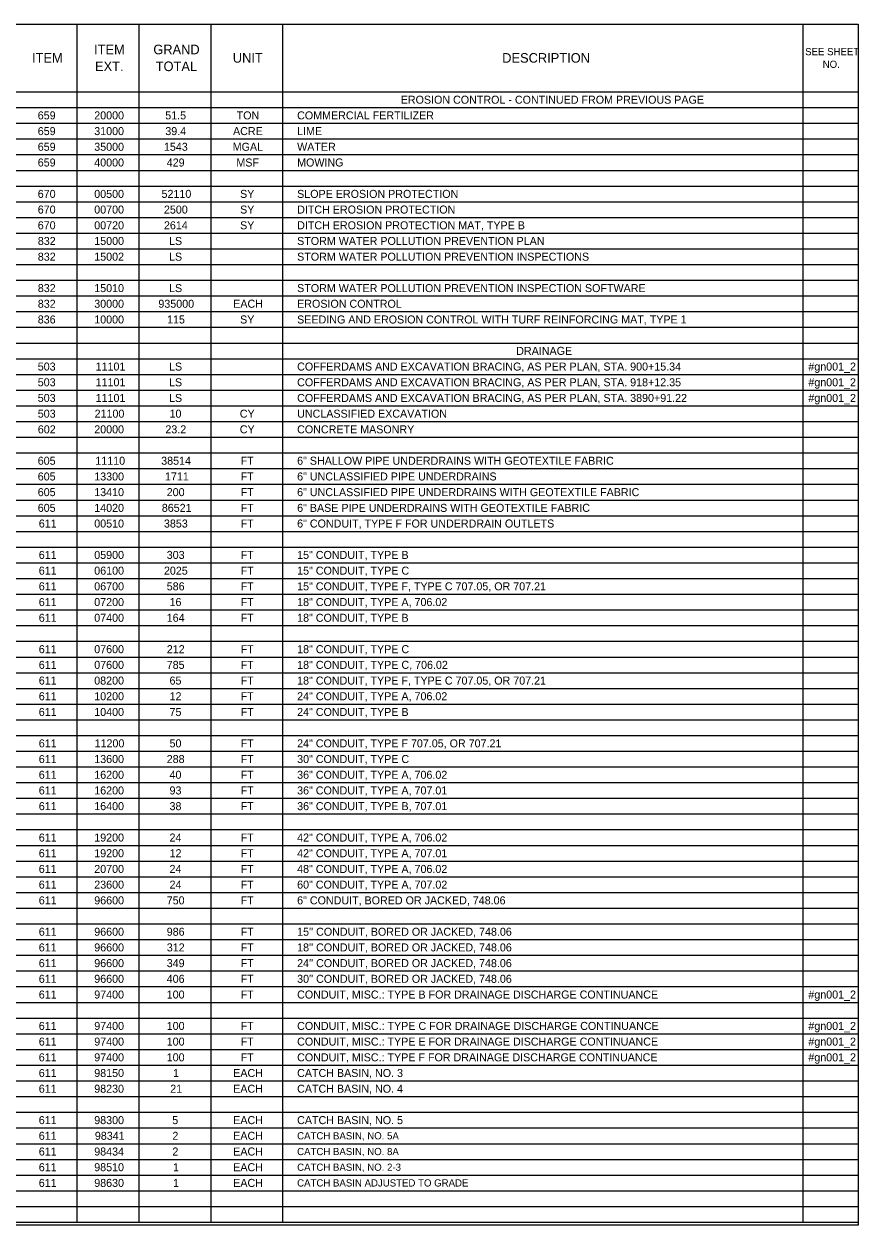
# Model space of a CAD drawing. Extents: x -542 to 295, y -281 to 32.
# Drawn here: x -400.45 to -385.84, y -40.59 to -19.59 of the extents above; entities that cross this region are included whole.
import ezdxf

# ---------------------------------------------------------------- set-up
doc = ezdxf.new("R2010")
doc.units = 0
for name, color, linetype in [('SC_Scratch1', 7, 'Continuous'), ('SH_Data', 7, 'Continuous'), ('SH_Text', 7, 'Continuous')]:
    doc.layers.add(name, color=color, linetype=linetype)

msp = doc.modelspace()

# ---------------------------------------------------------------- linework, layer by layer
at = {"layer": 'SC_Scratch1'}
msp.add_lwpolyline([(-416.359, -19.593), (-385.859, -19.593), (-385.859, -40.593), (-416.359, -40.593)], close=True, dxfattribs=at)
at = {"layer": 'SH_Data'}
for p, q in [((-416.359, -19.593), (-385.859, -19.593)), ((-399.523, -19.593), (-399.523, -40.543)), ((-398.437, -19.593), (-398.437, -40.543)), ((-397.182, -19.593), (-397.182, -40.543)), ((-395.926, -19.593), (-395.926, -40.543)), ((-386.827, -19.593), (-386.827, -40.543)), ((-385.859, -19.593), (-385.859, -40.543)), ((-416.359, -20.778), (-385.859, -20.778)), ((-416.359, -21.053), (-385.859, -21.053)), ((-416.359, -21.327), (-385.859, -21.327)), ((-416.359, -21.602), (-385.859, -21.602)), ((-416.359, -21.876), (-385.859, -21.876)), ((-416.359, -22.151), (-385.859, -22.151)), ((-416.359, -22.425), (-385.859, -22.425)), ((-416.359, -22.7), (-385.859, -22.7)), ((-416.359, -22.975), (-385.859, -22.975)), ((-416.359, -23.249), (-385.859, -23.249)), ((-416.359, -23.524), (-385.859, -23.524)), ((-416.359, -23.798), (-385.859, -23.798)), ((-416.359, -24.073), (-385.859, -24.073)), ((-416.359, -24.347), (-385.859, -24.347)), ((-416.359, -24.622), (-385.859, -24.622)), ((-416.359, -24.896), (-385.859, -24.896)), ((-416.359, -25.171), (-385.859, -25.171)), ((-416.359, -25.445), (-385.859, -25.445)), ((-416.359, -25.72), (-385.859, -25.72)), ((-416.359, -25.994), (-385.859, -25.994)), ((-416.359, -26.269), (-385.859, -26.269)), ((-416.359, -26.543), (-385.859, -26.543)), ((-416.359, -26.818), (-385.859, -26.818)), ((-416.359, -27.092), (-385.859, -27.092)), ((-416.359, -27.367), (-385.859, -27.367)), ((-416.359, -27.641), (-385.859, -27.641)), ((-416.359, -27.916), (-385.859, -27.916)), ((-416.359, -28.19), (-385.859, -28.19)), ((-416.359, -28.465), (-385.859, -28.465)), ((-416.359, -28.739), (-385.859, -28.739)), ((-416.359, -29.014), (-385.859, -29.014)), ((-416.359, -29.288), (-385.859, -29.288)), ((-416.359, -29.563), (-385.859, -29.563)), ((-416.359, -29.837), (-385.859, -29.837)), ((-416.359, -30.112), (-385.859, -30.112)), ((-416.359, -30.386), (-385.859, -30.386)), ((-416.359, -30.661), (-385.859, -30.661)), ((-416.359, -30.935), (-385.859, -30.935)), ((-416.359, -31.21), (-385.859, -31.21)), ((-416.359, -31.484), (-385.859, -31.484)), ((-416.359, -31.759), (-385.859, -31.759)), ((-416.359, -32.033), (-385.859, -32.033)), ((-416.359, -32.308), (-385.859, -32.308)), ((-416.359, -32.582), (-385.859, -32.582)), ((-416.359, -32.857), (-385.859, -32.857)), ((-416.359, -33.131), (-385.859, -33.131)), ((-416.359, -33.406), (-385.859, -33.406)), ((-416.359, -33.68), (-385.859, -33.68)), ((-416.359, -33.955), (-385.859, -33.955)), ((-416.359, -34.229), (-385.859, -34.229)), ((-416.359, -34.504), (-385.859, -34.504)), ((-416.359, -34.778), (-385.859, -34.778)), ((-416.359, -35.053), (-385.859, -35.053)), ((-416.359, -35.327), (-385.859, -35.327)), ((-416.359, -35.602), (-385.859, -35.602)), ((-416.359, -35.876), (-385.859, -35.876)), ((-416.359, -36.151), (-385.859, -36.151)), ((-416.359, -36.425), (-385.859, -36.425)), ((-416.359, -36.7), (-385.859, -36.7)), ((-416.359, -36.975), (-385.859, -36.975)), ((-416.359, -37.249), (-385.859, -37.249)), ((-416.359, -37.524), (-385.859, -37.524)), ((-416.359, -37.798), (-385.859, -37.798)), ((-416.359, -38.073), (-385.859, -38.073)), ((-416.359, -38.347), (-385.859, -38.347)), ((-416.359, -38.622), (-385.859, -38.622)), ((-416.359, -38.896), (-385.859, -38.896)), ((-416.359, -39.171), (-385.859, -39.171)), ((-416.359, -39.445), (-385.859, -39.445)), ((-416.359, -39.72), (-385.859, -39.72)), ((-416.359, -39.994), (-385.859, -39.994)), ((-416.359, -40.269), (-385.859, -40.269)), ((-416.359, -40.543), (-385.859, -40.543))]:
    msp.add_line(p, q, dxfattribs=at)

# ---------------------------------------------------------------- texts
at = {"layer": 'SH_Text'}
for s, height, p in [('ITEM', 0.168, (-400.307, -20.269)), ('ITEM', 0.168, (-399.222, -20.122)), ('GRAND ', 0.168, (-398.186, -20.122)), ('UNIT', 0.168, (-396.795, -20.269)), ('DESCRIPTION', 0.168, (-392.083, -20.269)), ('SEE SHEET ', 0.126, (-386.784, -20.138)), ('EXT.', 0.168, (-399.205, -20.416)), ('TOTAL', 0.168, (-398.144, -20.416)), ('NO.', 0.126, (-386.477, -20.359)), ('EROSION CONTROL - CONTINUED FROM PREVIOUS PAGE', 0.14, (-393.858, -20.986)), ('659', 0.14, (-400.207, -21.26)), ('20000', 0.14, (-399.219, -21.26)), ('51.5', 0.14, (-397.977, -21.26)), ('TON', 0.14, (-396.728, -21.26)), ('COMMERCIAL FERTILIZER', 0.14, (-395.67, -21.26)), ('659', 0.14, (-400.207, -21.535)), ('31000', 0.14, (-399.219, -21.535)), ('39.4', 0.14, (-397.976, -21.535)), ('ACRE', 0.14, (-396.791, -21.535)), ('LIME', 0.14, (-395.67, -21.535)), ('659', 0.14, (-400.207, -21.809)), ('35000', 0.14, (-399.219, -21.809)), ('1543', 0.14, (-398, -21.809)), ('MGAL', 0.14, (-396.797, -21.809)), ('WATER', 0.14, (-395.67, -21.809)), ('659', 0.14, (-400.207, -22.084)), ('40000', 0.14, (-399.219, -22.084)), ('429', 0.14, (-397.951, -22.084)), ('MSF', 0.14, (-396.733, -22.084)), ('MOWING', 0.14, (-395.67, -22.084)), ('670', 0.14, (-400.207, -22.633)), ('00500', 0.14, (-399.219, -22.633)), ('52110', 0.14, (-398.042, -22.633)), ('SY', 0.14, (-396.668, -22.633)), ('SLOPE EROSION PROTECTION', 0.14, (-395.67, -22.633)), ('670', 0.14, (-400.207, -22.907)), ('00700', 0.14, (-399.219, -22.907)), ('2500', 0.14, (-398, -22.907)), ('SY', 0.14, (-396.668, -22.907)), ('DITCH EROSION PROTECTION', 0.14, (-395.67, -22.907)), ('670', 0.14, (-400.207, -23.182)), ('00720', 0.14, (-399.219, -23.182)), ('2614', 0.14, (-398, -23.182)), ('SY', 0.14, (-396.668, -23.182)), ('DITCH EROSION PROTECTION MAT, TYPE B', 0.14, (-395.67, -23.182)), ('832', 0.14, (-400.206, -23.456)), ('15000', 0.14, (-399.219, -23.456)), ('LS', 0.14, (-397.911, -23.456)), ('STORM WATER POLLUTION PREVENTION PLAN', 0.14, (-395.67, -23.456)), ('832', 0.14, (-400.206, -23.731)), ('15002', 0.14, (-399.219, -23.731)), ('LS', 0.14, (-397.911, -23.731)), ('STORM WATER POLLUTION PREVENTION INSPECTIONS', 0.14, (-395.67, -23.731)), ('832', 0.14, (-400.206, -24.28)), ('15010', 0.14, (-399.219, -24.28)), ('LS', 0.14, (-397.911, -24.28)), ('STORM WATER POLLUTION PREVENTION INSPECTION SOFTWARE', 0.14, (-395.67, -24.28)), ('832', 0.14, (-400.206, -24.554)), ('30000', 0.14, (-399.219, -24.554)), ('935000', 0.14, (-398.097, -24.554)), ('EACH', 0.14, (-396.788, -24.554)), ('EROSION CONTROL', 0.14, (-395.67, -24.554)), ('836', 0.14, (-400.207, -24.829)), ('10000', 0.14, (-399.219, -24.829)), ('115', 0.14, (-397.945, -24.829)), ('SY', 0.14, (-396.668, -24.829)), ('SEEDING AND EROSION CONTROL WITH TURF REINFORCING MAT, TYPE 1', 0.14, (-395.67, -24.829)), ('DRAINAGE', 0.14, (-391.838, -25.378)), ('503', 0.14, (-400.207, -25.652)), ('11101', 0.14, (-399.195, -25.652)), ('LS', 0.14, (-397.911, -25.652)), ('COFFERDAMS AND EXCAVATION BRACING, AS PER PLAN, STA. 900+15.34', 0.14, (-395.67, -25.652)), ('#gn001_2', 0.14, (-386.728, -25.652)), ('503', 0.14, (-400.207, -25.927)), ('11101', 0.14, (-399.195, -25.927)), ('LS', 0.14, (-397.911, -25.927)), ('COFFERDAMS AND EXCAVATION BRACING, AS PER PLAN, STA. 918+12.35', 0.14, (-395.67, -25.927)), ('#gn001_2', 0.14, (-386.728, -25.927)), ('503', 0.14, (-400.207, -26.201)), ('11101', 0.14, (-399.195, -26.201)), ('LS', 0.14, (-397.911, -26.201)), ('COFFERDAMS AND EXCAVATION BRACING, AS PER PLAN, STA. 3890+91.22', 0.14, (-395.67, -26.201)), ('#gn001_2', 0.14, (-386.728, -26.201)), ('503', 0.14, (-400.207, -26.476)), ('21100', 0.14, (-399.213, -26.476)), ('10', 0.14, (-397.902, -26.476)), ('CY', 0.14, (-396.673, -26.476)), ('UNCLASSIFIED EXCAVATION', 0.14, (-395.67, -26.476)), ('602', 0.14, (-400.206, -26.75)), ('20000', 0.14, (-399.219, -26.75)), ('23.2', 0.14, (-397.975, -26.75)), ('CY', 0.14, (-396.673, -26.75)), ('CONCRETE MASONRY', 0.14, (-395.67, -26.75)), ('605', 0.14, (-400.207, -27.299)), ('11110', 0.14, (-399.2, -27.299)), ('38514', 0.14, (-398.048, -27.299)), ('FT', 0.14, (-396.658, -27.299)), ('6" SHALLOW PIPE UNDERDRAINS WITH GEOTEXTILE FABRIC', 0.14, (-395.67, -27.299)), ('605', 0.14, (-400.207, -27.574)), ('13300', 0.14, (-399.219, -27.574)), ('1711', 0.14, (-397.982, -27.574)), ('FT', 0.14, (-396.658, -27.574)), ('6" UNCLASSIFIED PIPE UNDERDRAINS', 0.14, (-395.67, -27.574)), ('605', 0.14, (-400.207, -27.848)), ('13410', 0.14, (-399.219, -27.848)), ('200', 0.14, (-397.951, -27.848)), ('FT', 0.14, (-396.658, -27.848)), ('6" UNCLASSIFIED PIPE UNDERDRAINS WITH GEOTEXTILE FABRIC', 0.14, (-395.67, -27.848)), ('605', 0.14, (-400.207, -28.123)), ('14020', 0.14, (-399.219, -28.123)), ('86521', 0.14, (-398.037, -28.123)), ('FT', 0.14, (-396.658, -28.123)), ('6" BASE PIPE UNDERDRAINS WITH GEOTEXTILE FABRIC', 0.14, (-395.67, -28.123)), ('611', 0.14, (-400.189, -28.397)), ('00510', 0.14, (-399.219, -28.397)), ('3853', 0.14, (-398, -28.397)), ('FT', 0.14, (-396.658, -28.397)), ('6" CONDUIT, TYPE F FOR UNDERDRAIN OUTLETS', 0.14, (-395.67, -28.397)), ('611', 0.14, (-400.189, -28.946)), ('05900', 0.14, (-399.219, -28.946)), ('303', 0.14, (-397.951, -28.946)), ('FT', 0.14, (-396.658, -28.946)), ('15" CONDUIT, TYPE B', 0.14, (-395.67, -28.946)), ('611', 0.14, (-400.189, -29.221)), ('06100', 0.14, (-399.219, -29.221)), ('2025', 0.14, (-398, -29.221)), ('FT', 0.14, (-396.658, -29.221)), ('15" CONDUIT, TYPE C', 0.14, (-395.67, -29.221)), ('611', 0.14, (-400.189, -29.495)), ('06700', 0.14, (-399.219, -29.495)), ('586', 0.14, (-397.951, -29.495)), ('FT', 0.14, (-396.658, -29.495)), ('15" CONDUIT, TYPE F, TYPE C 707.05, OR 707.21', 0.14, (-395.67, -29.495)), ('611', 0.14, (-400.189, -29.77)), ('07200', 0.14, (-399.219, -29.77)), ('16', 0.14, (-397.902, -29.77)), ('FT', 0.14, (-396.658, -29.77)), ('18" CONDUIT, TYPE A, 706.02', 0.14, (-395.67, -29.77)), ('611', 0.14, (-400.189, -30.045)), ('07400', 0.14, (-399.219, -30.045)), ('164', 0.14, (-397.951, -30.045)), ('FT', 0.14, (-396.658, -30.045)), ('18" CONDUIT, TYPE B', 0.14, (-395.67, -30.045)), ('611', 0.14, (-400.189, -30.594)), ('07600', 0.14, (-399.219, -30.594)), ('212', 0.14, (-397.95, -30.594)), ('FT', 0.14, (-396.658, -30.594)), ('18" CONDUIT, TYPE C', 0.14, (-395.67, -30.594)), ('611', 0.14, (-400.189, -30.868)), ('07600', 0.14, (-399.219, -30.868)), ('785', 0.14, (-397.951, -30.868)), ('FT', 0.14, (-396.658, -30.868)), ('18" CONDUIT, TYPE C, 706.02', 0.14, (-395.67, -30.868)), ('611', 0.14, (-400.189, -31.143)), ('08200', 0.14, (-399.219, -31.143)), ('65', 0.14, (-397.902, -31.143)), ('FT', 0.14, (-396.658, -31.143)), ('18" CONDUIT, TYPE F, TYPE C 707.05, OR 707.21', 0.14, (-395.67, -31.143)), ('611', 0.14, (-400.189, -31.417)), ('10200', 0.14, (-399.219, -31.417)), ('12', 0.14, (-397.901, -31.417)), ('FT', 0.14, (-396.658, -31.417)), ('24" CONDUIT, TYPE A, 706.02', 0.14, (-395.67, -31.417)), ('611', 0.14, (-400.189, -31.692)), ('10400', 0.14, (-399.219, -31.692)), ('75', 0.14, (-397.902, -31.692)), ('FT', 0.14, (-396.658, -31.692)), ('24" CONDUIT, TYPE B', 0.14, (-395.67, -31.692)), ('611', 0.14, (-400.189, -32.241)), ('11200', 0.14, (-399.213, -32.241)), ('50', 0.14, (-397.902, -32.241)), ('FT', 0.14, (-396.658, -32.241)), ('24" CONDUIT, TYPE F 707.05, OR 707.21', 0.14, (-395.67, -32.241)), ('611', 0.14, (-400.189, -32.515)), ('13600', 0.14, (-399.219, -32.515)), ('288', 0.14, (-397.951, -32.515)), ('FT', 0.14, (-396.658, -32.515)), ('30" CONDUIT, TYPE C', 0.14, (-395.67, -32.515)), ('611', 0.14, (-400.189, -32.79)), ('16200', 0.14, (-399.219, -32.79)), ('40', 0.14, (-397.902, -32.79)), ('FT', 0.14, (-396.658, -32.79)), ('36" CONDUIT, TYPE A, 706.02', 0.14, (-395.67, -32.79)), ('611', 0.14, (-400.189, -33.064)), ('16200', 0.14, (-399.219, -33.064)), ('93', 0.14, (-397.902, -33.064)), ('FT', 0.14, (-396.658, -33.064)), ('36" CONDUIT, TYPE A, 707.01', 0.14, (-395.67, -33.064)), ('611', 0.14, (-400.189, -33.339)), ('16400', 0.14, (-399.219, -33.339)), ('38', 0.14, (-397.902, -33.339)), ('FT', 0.14, (-396.658, -33.339)), ('36" CONDUIT, TYPE B, 707.01', 0.14, (-395.67, -33.339)), ('611', 0.14, (-400.189, -33.888)), ('19200', 0.14, (-399.219, -33.888)), ('24', 0.14, (-397.902, -33.888)), ('FT', 0.14, (-396.658, -33.888)), ('42" CONDUIT, TYPE A, 706.02', 0.14, (-395.67, -33.888)), ('611', 0.14, (-400.189, -34.162)), ('19200', 0.14, (-399.219, -34.162)), ('12', 0.14, (-397.901, -34.162)), ('FT', 0.14, (-396.658, -34.162)), ('42" CONDUIT, TYPE A, 707.01', 0.14, (-395.67, -34.162)), ('611', 0.14, (-400.189, -34.437)), ('20700', 0.14, (-399.219, -34.437)), ('24', 0.14, (-397.902, -34.437)), ('FT', 0.14, (-396.658, -34.437)), ('48" CONDUIT, TYPE A, 706.02', 0.14, (-395.67, -34.437)), ('611', 0.14, (-400.189, -34.711)), ('23600', 0.14, (-399.219, -34.711)), ('24', 0.14, (-397.902, -34.711)), ('FT', 0.14, (-396.658, -34.711)), ('60" CONDUIT, TYPE A, 707.02', 0.14, (-395.67, -34.711)), ('611', 0.14, (-400.189, -34.986)), ('96600', 0.14, (-399.219, -34.986)), ('750', 0.14, (-397.951, -34.986)), ('FT', 0.14, (-396.658, -34.986)), ('6" CONDUIT, BORED OR JACKED, 748.06', 0.14, (-395.67, -34.986)), ('611', 0.14, (-400.189, -35.535)), ('96600', 0.14, (-399.219, -35.535)), ('986', 0.14, (-397.951, -35.535)), ('FT', 0.14, (-396.658, -35.535)), ("15'' CONDUIT, BORED OR JACKED, 748.06", 0.14, (-395.67, -35.535)), ('611', 0.14, (-400.189, -35.809)), ('96600', 0.14, (-399.219, -35.809)), ('312', 0.14, (-397.95, -35.809)), ('FT', 0.14, (-396.658, -35.809)), ("18'' CONDUIT, BORED OR JACKED, 748.06", 0.14, (-395.67, -35.809)), ('611', 0.14, (-400.189, -36.084)), ('96600', 0.14, (-399.219, -36.084)), ('349', 0.14, (-397.951, -36.084)), ('FT', 0.14, (-396.658, -36.084)), ("24'' CONDUIT, BORED OR JACKED, 748.06", 0.14, (-395.67, -36.084)), ('611', 0.14, (-400.189, -36.358)), ('96600', 0.14, (-399.219, -36.358)), ('406', 0.14, (-397.951, -36.358)), ('FT', 0.14, (-396.658, -36.358)), ("30'' CONDUIT, BORED OR JACKED, 748.06", 0.14, (-395.67, -36.358)), ('611', 0.14, (-400.189, -36.633)), ('97400', 0.14, (-399.219, -36.633)), ('100', 0.14, (-397.951, -36.633)), ('FT', 0.14, (-396.658, -36.633)), ('CONDUIT, MISC.: TYPE B FOR DRAINAGE DISCHARGE CONTINUANCE', 0.14, (-395.67, -36.633)), ('#gn001_2', 0.14, (-386.728, -36.633)), ('611', 0.14, (-400.189, -37.182)), ('97400', 0.14, (-399.219, -37.182)), ('100', 0.14, (-397.951, -37.182)), ('FT', 0.14, (-396.658, -37.182)), ('CONDUIT, MISC.: TYPE C FOR DRAINAGE DISCHARGE CONTINUANCE', 0.14, (-395.67, -37.182)), ('#gn001_2', 0.14, (-386.728, -37.182)), ('611', 0.14, (-400.189, -37.456)), ('97400', 0.14, (-399.219, -37.456)), ('100', 0.14, (-397.951, -37.456)), ('FT', 0.14, (-396.658, -37.456)), ('CONDUIT, MISC.: TYPE E FOR DRAINAGE DISCHARGE CONTINUANCE', 0.14, (-395.67, -37.456)), ('#gn001_2', 0.14, (-386.728, -37.456)), ('611', 0.14, (-400.189, -37.731)), ('97400', 0.14, (-399.219, -37.731)), ('100', 0.14, (-397.951, -37.731)), ('CONDUIT, MISC.: TYPE F FOR DRAINAGE DISCHARGE CONTINUANCE', 0.14, (-395.67, -37.731)), ('#gn001_2', 0.14, (-386.728, -37.731)), ('FT', 0.14, (-396.658, -37.731)), ('611', 0.14, (-400.189, -38.005)), ('98150', 0.14, (-399.219, -38.005)), ('1', 0.14, (-397.841, -38.005)), ('EACH', 0.14, (-396.788, -38.005)), ('CATCH BASIN, NO. 3', 0.14, (-395.67, -38.005)), ('611', 0.14, (-400.189, -38.28)), ('98230', 0.14, (-399.219, -38.28)), ('21', 0.14, (-397.89, -38.28)), ('EACH', 0.14, (-396.788, -38.28)), ('CATCH BASIN, NO. 4', 0.14, (-395.67, -38.28)), ('611', 0.14, (-400.189, -38.829)), ('98300', 0.14, (-399.219, -38.829)), ('5', 0.14, (-397.854, -38.829)), ('EACH', 0.14, (-396.788, -38.829)), ('CATCH BASIN, NO. 5', 0.14, (-395.67, -38.829)), ('611', 0.14, (-400.189, -39.103)), ('98341', 0.14, (-399.208, -39.103)), ('2', 0.14, (-397.852, -39.103)), ('EACH', 0.14, (-396.788, -39.103)), ('CATCH BASIN, NO. 5A', 0.126, (-395.67, -39.096)), ('611', 0.14, (-400.189, -39.378)), ('98434', 0.14, (-399.219, -39.378)), ('2', 0.14, (-397.852, -39.378)), ('EACH', 0.14, (-396.788, -39.378)), ('CATCH BASIN, NO. 8A', 0.126, (-395.67, -39.371)), ('611', 0.14, (-400.189, -39.652)), ('98510', 0.14, (-399.219, -39.652)), ('1', 0.14, (-397.841, -39.652)), ('EACH', 0.14, (-396.788, -39.652)), ('CATCH BASIN, NO. 2-3', 0.126, (-395.67, -39.645)), ('611', 0.14, (-400.189, -39.927)), ('98630', 0.14, (-399.219, -39.927)), ('1', 0.14, (-397.841, -39.927)), ('EACH', 0.14, (-396.788, -39.927)), ('CATCH BASIN ADJUSTED TO GRADE', 0.126, (-395.67, -39.92))]:
    msp.add_text(s, height=height, dxfattribs=at).set_placement(p)

doc.saveas('drawing.dxf')
